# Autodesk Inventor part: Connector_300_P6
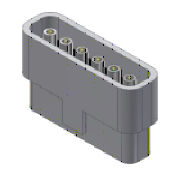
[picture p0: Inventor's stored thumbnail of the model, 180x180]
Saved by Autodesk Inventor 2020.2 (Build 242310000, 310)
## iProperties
Manager: www.cadconsulting.pl
Company: Fabian Stasiak CAD Consulting
Created: 2014-10
Part Number: Connector_300_P6
Material: Ogólny
Description: Wtyk typ 300, ALPHA
Document SubType Name: Modeling
Standard: ALPHA-100/2012
Designer: F.Stasiak
Manufacturer: ALPHA
Standards Organization: ISO
Language: pl-PL
Size Designation: Connector_300_P6
Categories: <MemberInstance><Categories><Category DisplayName="Kable i wiązki przewodów" InternalName="e4a7e005-5e42-4d16-b293-125e7f0d0512" Mnemonic="CABLEANDHARNESS"><Cat
Density: 1 g/cm^3
Appearance: Śnieg
Catalog Web Link: www.expertbooks.pl
IsCustomPart: 0
Author: F.Stasiak
Subject: Zbiór ćwiczeń. Autodesk Inventor 2020. Kurs Professional
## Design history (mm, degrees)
sketch "Szkic1"
  geometry: L1 (0, 0)-(30, 0); L2 (0, 2.5)-(30, 2.5); L3 (30, 2.5)-(30, -2.5); L4 (30, -2.5)-(0, -2.5); L5 (0, -2.5)-(0, 2.5); 7 further points
  constraints: 10 end point, 2 horizontal, 2 parallel, 1 coincident, 1 midpoint, 1 perpendicular
  dimensions: "d0" = 5 distance of point (7.5, 0) point (2.5, 0); "d1" = 5 distance of point (12.5, 0) point (7.5, 0) (= d0); "d2" = 5 distance of point (17.5, 0) point (12.5, 0) (= d0); "d3" = 5 distance of point (22.5, 0) point (17.5, 0) (= d0); "d4" = 5 distance of point (22.5, 0) point (27.5, 0) (= d0); "d16" = 2.5 distance of point (2.5, 0) L1.start; "d17" = 2.5 distance of point (27.5, 0) L1.end (= d16); "d18" = 5 distance of L4.end L2.start; "d19" = 30 distance of L3.end L4.end (= 0.5 x LPINÓW)
node "Oś konstrukcyjna1"
node "Oś konstrukcyjna2"
node "Oś konstrukcyjna3"
node "Oś konstrukcyjna4"
node "Oś konstrukcyjna5"
node "Oś konstrukcyjna6"
extrude "Wyciągnięcie proste3" new body sketch "Szkic1" distance "d20" = 3; taper "d21" = 0 deg
sketch "Szkic3"
  geometry: C1 r 1 at (2.5, 0); 2 further points
  constraints: 1 centre point, 1 coincident
  dimensions: "d22" = 2 diameter of C1
extrude "Wyciągnięcie proste4" join sketch "Szkic3" distance "d23" = 5; taper "d24" = 0 deg; dims "d29" = 15, "d30" = 0
sketch "Szkic4"
  geometry: C1 r 1.5 at (0, 0)
  constraints: 1 centre point
  dimensions: "d31" = 3 diameter of C1
extrude "Wyciągnięcie proste5" join sketch "Szkic4" stored distance "d32" = 0; taper "d33" = 0 deg
sketch "Szkic5"
  geometry: C1 r 0.9 at (0, 0)
  constraints: 1 centre point
  dimensions: "d34" = 1.8 diameter of C1
extrude "Wyciągnięcie proste6" cut sketch "Szkic5" distance "d35" = 7; taper "d36" = 0 deg
fillet "Zaokrąglenie3" dims "d45" = 1
pattern_linear "Szyk prostokątny2" dims "d27" = 5
node "Płaszczyzna konstrukcyjna1"
sketch "Szkic6"
  geometry: L1 (0, -2.5)-(30, -2.5) reference; L2 (30, -2.5)-(30, 2.5) reference; L3 (30, 2.5)-(0, 2.5) reference; L4 (0, 2.5)-(0, -2.5) reference; L5 (31.5, -4)-(-1.5, -4); L6 (-1.5, -4)-(-1.5, 4); L7 (-1.5, 4)-(31.5, 4); L8 (31.5, 4)-(31.5, -4)
  constraints: 8 end point, 3 other
  dimensions: "d37" = 1.5 distance between parallel lines of L5 L1
extrude "Wyciągnięcie proste7" join sketch "Szkic6" distance "d38" = 15.25; taper "d39" = 0 deg
fillet "Zaokrąglenie1" dims "d40" = 1
fillet "Zaokrąglenie2" dims "d41" = 2.5
chamfer "Faza1" distance "d42" = 1.05; stored, may be unused: second distance "d43" = 11, angle "d44" = 45 deg
sketch "Szkic7"
  geometry: L1 (-1.5, -1.5)-(-1.5, 1.5) reference; L2 (29, -4)-(1, -4) reference; L3 (31.5, 1.5)-(31.5, -1.5) reference; L4 (1, 4)-(29, 4) reference; L5 (-3, -1.5)-(-3, 1.5); L6 (1, 5.5)-(29, 5.5); L7 (33, 1.5)-(33, -1.5); L8 (29, -5.5)-(1, -5.5); C1 r 1.5 at (12.5, 0) reference; C2 r 1.5 at (7.5, 0) reference; C3 r 1.5 at (2.5, 0) reference; A1 r 2.5 centre (1, 1.5) between (1, 4) and (-1.5, 1.5) reference; A2 r 2.5 centre (1, -1.5) between (-1.5, -1.5) and (1, -4) reference; A3 r 2.5 centre (29, -1.5) between (29, -4) and (31.5, -1.5) reference; A4 r 2.5 centre (29, 1.5) between (31.5, 1.5) and (29, 4) reference; A5 r 4 centre (1, -1.5) between (-3, -1.5) and (1, -5.5); A6 r 4 centre (1, 1.5) between (1, 5.5) and (-3, 1.5); A7 r 4 centre (29, 1.5) between (33, 1.5) and (29, 5.5); A8 r 4 centre (29, -1.5) between (29, -5.5) and (33, -1.5)
  constraints: 8 end point, 8 point on circle, 4 centre point, 7 other
  dimensions: "d46" = 1.5 distance between parallel lines of L2 L8
extrude "Wyciągnięcie proste8" join sketch "Szkic7" stored distance "d47" = 12; taper "d48" = 0 deg
sketch "Szkic8"
  geometry: L1 (-1, 4)-(-29, 4) reference; L2 (1.5, -1.5)-(1.5, 1.5) reference; L3 (-29, -4)-(-1, -4) reference; L4 (-31.5, 1.5)-(-31.5, -1.5) reference; L5 (3, -1.5)-(3, 1.5) reference; L6 (-1, 5.5)-(-29, 5.5) reference; L7 (-33, 1.5)-(-33, -1.5) reference; L8 (-29, -5.5)-(-1, -5.5) reference; L9 (-12, -5.5)-(-18, -5.5); L10 (-18, -5.5)-(-18, -4); L11 (-18, -4)-(-12, -4); L12 (-12, -4)-(-12, -5.5); A1 r 2.5 centre (-1, 1.5) between (1.5, 1.5) and (-1, 4) reference; A2 r 2.5 centre (-1, -1.5) between (-1, -4) and (1.5, -1.5) reference; A3 r 2.5 centre (-29, -1.5) between (-31.5, -1.5) and (-29, -4) reference; A4 r 2.5 centre (-29, 1.5) between (-29, 4) and (-31.5, 1.5) reference; A5 r 4 centre (-1, -1.5) between (-1, -5.5) and (3, -1.5) reference; A6 r 4 centre (-1, 1.5) between (3, 1.5) and (-1, 5.5) reference; A7 r 4 centre (-29, 1.5) between (-29, 5.5) and (-33, 1.5) reference; A8 r 4 centre (-29, -1.5) between (-33, -1.5) and (-29, -5.5) reference; 2 further points
  constraints: 8 end point, 4 midpoint, 2 parallel, 1 horizontal, 1 perpendicular
  dimensions: "d49" = 6 distance of L9.start L9.end
extrude "Wyciągnięcie proste9" join sketch "Szkic8" distance "d50" = 6.5; taper "d51" = 0 deg
node "Punkt konstrukcyjny2"
node "Punkt konstrukcyjny3"
node "Punkt konstrukcyjny4"
node "Punkt konstrukcyjny5"
node "Punkt konstrukcyjny6"
node "Punkt konstrukcyjny7"
node "1"
node "2"
node "3"
node "4"
node "5"
node "6"
node "Bryła2"
node "Pętla rzutowana1"
node "Pętla rzutowana2"
other parameters: "d28" = 8
